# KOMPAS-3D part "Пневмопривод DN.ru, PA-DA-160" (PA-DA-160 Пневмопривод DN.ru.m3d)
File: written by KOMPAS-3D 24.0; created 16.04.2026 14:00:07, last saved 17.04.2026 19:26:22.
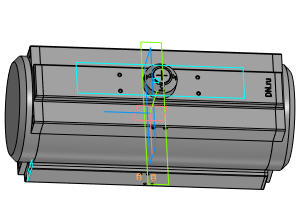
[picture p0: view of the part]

Document properties: Автор: DN.ru; Полное имя файла: C:\Работа\PA-DA-х Пневмопривод DN.ru\160\исходные материалы\PA-DA-160 Пневмопривод DN.ru.m3d

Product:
- Body: Тело 1  | qty 1
    Масса: 103.939384
- Body: Тело 2  | qty 1
    Масса: 103.939384
- Part/product: Пневмопривод DN.ru  | designation PA-DA-160
    Масса: 20
    Раздел спецификации: Прочие изделия
    Примечание: D290-00299

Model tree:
1. Эскиз:1
2. Элемент выдавливания:1
3. Эскиз:2  (with: Ребро.Элемент выдавливания:1)
4. Элемент выдавливания:2
5. Эскиз:3  (with: Ребро.Элемент выдавливания:2)
6. Элемент выдавливания:3  (with: Грань.Элемент выдавливания:2)
     Смещение 1 = -2; Расстояние 2 = 207; Смещение 2 = -2
7. Эскиз:4  (with: Грань.Элемент выдавливания:3)
8. Элемент выдавливания:4
9. Эскиз:6  (with: Ребро.Элемент выдавливания:2)
10. Элемент выдавливания:6
11. Отверстие:2  (with: Грань.Элемент выдавливания:6)
     Глубина выреза = 10; Диаметр отверстия = 5; Угол конуса дна = 120; Расстояние 2 = 7
12. Массив по сетке:2  (with: Отверстие:2)  (3 pattern instances)
     Шаг 1 = 12; Угол раствора = 90; Шаг 2 = 32
13. Массив по сетке:3  (with: Отверстие:2)  (2 pattern instances)
     Шаг 1 = 32; Угол раствора = 90; Шаг 2 = 12
14. Отверстие:3  (with: Грань.Элемент выдавливания:6, Ребро.Элемент выдавливания:6)  (labels: W 1/4'')
     Глубина выреза = 10; Диаметр отверстия = 4.72357; Угол конуса дна = 120; Расстояние 1 = 12; Расстояние 2 = 23
15. W 1/4''  (with: Грань.Отверстие:3, Грань.Элемент выдавливания:6)  (labels: cil5_ex_DIN 477 BSW coarse)
     Длина резьбы = 8; Шаг резьбы = 1.27; Номинальный диаметр резьбы = 6.35
16. Массив по сетке:4  (with: Отверстие:3)  (labels: W 1/4'')  (2 pattern instances)
17. Эскиз:7  (with: Грань.Элемент выдавливания:2)
18. Элемент выдавливания:7
19. Эскиз:8  (with: Грань.Элемент выдавливания:2, Ребро.Элемент выдавливания:2)
20. Элемент выдавливания:8  (with: Грань.Элемент выдавливания:6)
     Расстояние 2 = 4
21. Отверстие:4  (with: Грань.Элемент выдавливания:2)
     Глубина выреза = 7; Диаметр отверстия = 5; Угол конуса дна = 118; Расстояние 1 = 6; Расстояние 2 = 10; Диаметр зенковки = 7; Глубина зенковки = 1; Угол зенковки = 90
22. Массив по сетке:5  (with: Отверстие:4)  (2 pattern instances)
     Шаг 1 = 20; Угол раствора = 90
23. Отверстие:5  (with: Грань.Элемент выдавливания:3)
     Глубина выреза = 10; Диаметр отверстия = 5; Угол конуса дна = 120; Диаметр зенковки = 7; Глубина зенковки = 1; Угол зенковки = 90
24. Массив по сетке:6  (with: Отверстие:5)  (4 pattern instances)
     Угол раствора = 90
25. Фаска:1  (with: Ребро.Элемент выдавливания:4)
     Угол = 45; Длина 1 = 10; Длина 2 = 10
26. Скругление:2  (with: Ребро.Элемент выдавливания:3)
     Радиус = 2
27. Скругление:3  (with: Ребро.Элемент выдавливания:6)
     Радиус = 3
28. Скругление:4  (with: Ребро.Элемент выдавливания:8, Ребро.Элемент выдавливания:2)
     Радиус = 2
29. Скругление:5  (with: Ребро.Элемент выдавливания:6)
     Радиус = 1
30. Смещенная плоскость:1  (with: Грань.Элемент выдавливания:3)
31. Эскиз:9
32. Элемент выдавливания:9  (with: Грань.Фаска:1)
     Расстояние 1 = 35.1642; Смещение 1 = 1
33. Смещенная плоскость:2  (with: Грань.Элемент выдавливания:4)
     Расстояние = 0.5
34. Эскиз:10
35. Элемент выдавливания:10
     Расстояние 1 = 18.4142
36. Эскиз:11  (with: Грань.Элемент выдавливания:4)
37. Элемент выдавливания:11
     Расстояние 1 = 1
38. Эскиз:12  (with: Грань.Элемент выдавливания:11, Ребро.Элемент выдавливания:11)
39. Элемент выдавливания:12  (with: Грань.Элемент выдавливания:4)
     Расстояние 2 = 1
40. Эскиз:13  (with: Грань.Элемент выдавливания:11)
41. Элемент выдавливания:13  (with: Грань.Элемент выдавливания:4)
     Расстояние 2 = 1
42. Скругление:7  (with: Ребро.Элемент выдавливания:11)
     Радиус = 1
43. Скругление:8  (with: Ребро.Элемент выдавливания:8, Ребро.Элемент выдавливания:2)
     Радиус = 2
44. Эскиз:14  (with: Грань.Элемент выдавливания:3)
45. Элемент выдавливания:14  (with: Грань.Фаска:1)
     Расстояние 1 = 46.6414; Смещение 1 = 0.1
46. Эскиз:15  (with: Грань.Элемент выдавливания:3, Ребро.Скругление:2)
47. Элемент выдавливания:15
     Расстояние 2 = 0.1
48. Отверстие:6  (with: Грань.Элемент выдавливания:2, Ребро.Элемент выдавливания:2)
     Глубина выреза = 10; Диаметр отверстия = 8; Угол конуса дна = 118; Расстояние 1 = 10; Расстояние 2 = 10; Диаметр цековки = 15; Глубина цековки = 5
49. Зеркальный массив:1
50. Экземпляр ( 1 )
51. Экземпляр ( 2 )  (with: Отверстие:6)
52. Зеркальный массив:2  (with: Экземпляр ( 1 ), Экземпляр ( 2 ), Отверстие:6)
53. Зеркальный массив:3  (with: Экземпляр ( 1 ), Экземпляр ( 2 ), Зеркальный массив:2, Отверстие:6)
54. Зеркальный массив:4  (with: Экземпляр ( 1 ), Экземпляр ( 2 ), Зеркальный массив:1, Отверстие:6, Зеркальный массив:3, Зеркальный массив:2)
55. Фаска:2  (with: Ребро.Элемент выдавливания:7)
     Угол = 45; Длина 1 = 1; Длина 2 = 1
56. Фаска:3  (with: Ребро.Элемент выдавливания:1)
     Угол = 45; Длина 1 = 10; Длина 2 = 10
57. Смещенная плоскость:3  (with: Грань.Элемент выдавливания:6)
     Расстояние = 5
58. Эскиз:16
59. Элемент выдавливания:16
     Расстояние 2 = 0.1
60. Зеркальный массив:5  (with: Экземпляр ( 1 ), Экземпляр ( 2 ), Элемент выдавливания:16)

Expressions: H/2; -G/2; (E-D-4.5)/2; v2053*2
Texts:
  PA-DA-160
  GOST 26.020 Pr3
